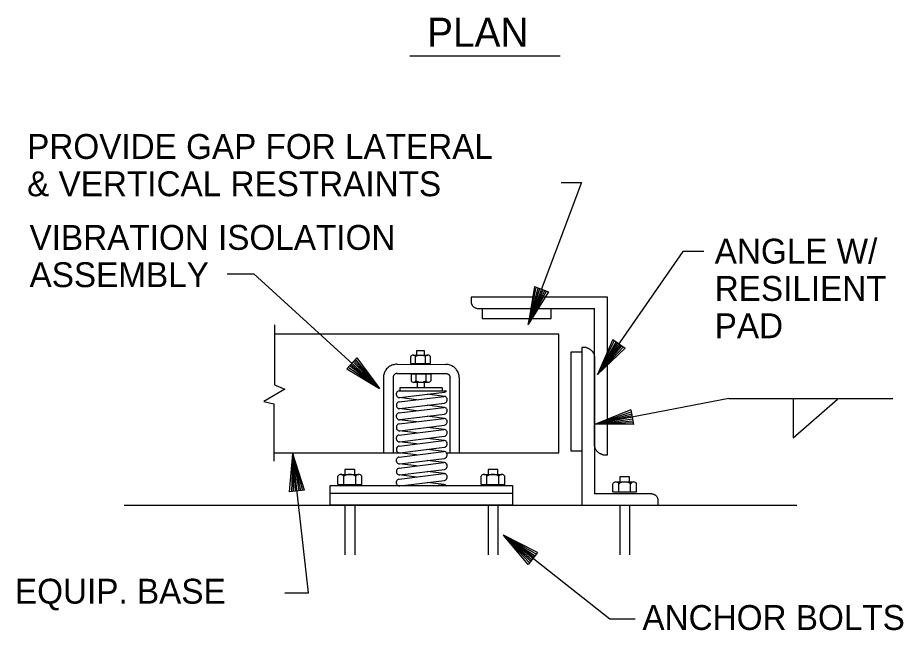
# Model space of a CAD drawing. Extents: x 9999.96 to 10005.26, y 9999.88 to 10002.38.
# Drawn here: x 10002.2227 to 10002.5788, y 10001.8155 to 10002.0618 of the extents above; entities that cross this region are included whole.
import ezdxf

# ---------------------------------------------------------------- set-up
doc = ezdxf.new("R2010")
doc.units = 0
doc.layers.add('Level 2', color=7, linetype='Continuous')

msp = doc.modelspace()

# ---------------------------------------------------------------- linework, layer by layer
at = {"layer": 'Level 2'}
for p, q in [((10002.3804, 10002.04644), (10002.44085, 10002.04644)), ((10002.43048, 10001.95363), (10002.42802, 10001.93847)), ((10002.42802, 10001.93847), (10002.4312, 10001.95335)), ((10002.42802, 10001.93847), (10002.43199, 10001.95308)), ((10002.42802, 10001.93847), (10002.43261, 10001.95282)), ((10002.43327, 10001.95259), (10002.42802, 10001.93847)), ((10002.42802, 10001.93847), (10002.43398, 10001.95231)), ((10002.42802, 10001.93847), (10002.43468, 10001.95206)), ((10002.42802, 10001.93847), (10002.43535, 10001.9518)), ((10002.43611, 10001.9515), (10002.42802, 10001.93847)), ((10002.43048, 10001.95363), (10002.43611, 10001.9515)), ((10002.4598, 10001.94941), (10002.40499, 10001.94941)), ((10002.40499, 10001.94941), (10002.40499, 10001.94773)), ((10002.4598, 10001.88604), (10002.4598, 10001.94941)), ((10002.40771, 10001.94486), (10002.45464, 10001.94486)), ((10002.45464, 10001.88964), (10002.45464, 10001.94486)), ((10002.44031, 10001.93446), (10002.32593, 10001.93446)), ((10002.44031, 10001.88671), (10002.44031, 10001.93446)), ((10002.46198, 10001.9324), (10002.45586, 10001.91831)), ((10002.45586, 10001.91831), (10002.4626, 10001.93196)), ((10002.45586, 10001.91831), (10002.46331, 10001.9315)), ((10002.45586, 10001.91831), (10002.46384, 10001.93109)), ((10002.46443, 10001.93071), (10002.45586, 10001.91831)), ((10002.45586, 10001.91831), (10002.46504, 10001.93027)), ((10002.45586, 10001.91831), (10002.46567, 10001.92985)), ((10002.46198, 10001.9324), (10002.46692, 10001.92895)), ((10002.44947, 10001.9291), (10002.44947, 10001.86574)), ((10002.4513, 10001.9291), (10002.44947, 10001.9291)), ((10002.45586, 10001.91831), (10002.46625, 10001.92943)), ((10002.46692, 10001.92895), (10002.45586, 10001.91831)), ((10002.35503, 10001.9206), (10002.3591, 10001.92505)), ((10002.35703, 10001.92282), (10002.36819, 10001.91269)), ((10002.36819, 10001.91269), (10002.35755, 10001.92336)), ((10002.36819, 10001.91269), (10002.35805, 10001.92393)), ((10002.36819, 10001.91269), (10002.35854, 10001.92446)), ((10002.3591, 10001.92505), (10002.36819, 10001.91269)), ((10002.38075, 10001.92279), (10002.38075, 10001.92554)), ((10002.38075, 10001.92279), (10002.38865, 10001.92279)), ((10002.38174, 10001.92614), (10002.38766, 10001.92614)), ((10002.38271, 10001.92279), (10002.38271, 10001.92554)), ((10002.38668, 10001.92279), (10002.38668, 10001.92554)), ((10002.38865, 10001.92279), (10002.38865, 10001.92552)), ((10002.45464, 10001.92551), (10002.45464, 10001.87028)), ((10002.35503, 10001.9206), (10002.36819, 10001.91269)), ((10002.36819, 10001.91269), (10002.35555, 10001.92118)), ((10002.36819, 10001.91269), (10002.3561, 10001.92181)), ((10002.36819, 10001.91269), (10002.35657, 10001.92229)), ((10002.37523, 10001.92241), (10002.3949, 10001.92236)), ((10002.36977, 10001.91704), (10002.36977, 10001.88671)), ((10002.37363, 10001.91714), (10002.37363, 10001.88671)), ((10002.37529, 10001.91871), (10002.39491, 10001.91871)), ((10002.38088, 10001.91851), (10002.38877, 10001.91851)), ((10002.38088, 10001.91851), (10002.38088, 10001.91576)), ((10002.38283, 10001.91851), (10002.38283, 10001.91576)), ((10002.3868, 10001.91851), (10002.3868, 10001.91576)), ((10002.38877, 10001.91851), (10002.38877, 10001.91578)), ((10002.39652, 10001.91704), (10002.39652, 10001.88671)), ((10002.40022, 10001.91704), (10002.40022, 10001.88671)), ((10002.39343, 10001.91298), (10002.3764, 10001.91298)), ((10002.3764, 10001.91298), (10002.3764, 10001.91173)), ((10002.38186, 10001.91517), (10002.38778, 10001.91517)), ((10002.38327, 10001.9152), (10002.38327, 10001.91296)), ((10002.38631, 10001.91296), (10002.38631, 10001.9152)), ((10002.39343, 10001.91298), (10002.39343, 10001.91173)), ((10002.37602, 10001.91173), (10002.39514, 10001.91173)), ((10002.38304, 10001.90816), (10002.37602, 10001.90901)), ((10002.37603, 10001.90729), (10002.39406, 10001.90951)), ((10002.37629, 10001.90902), (10002.39431, 10001.91124)), ((10002.39432, 10001.90951), (10002.38729, 10001.91038)), ((10002.50869, 10001.9086), (10002.45499, 10001.89832)), ((10002.50869, 10001.9086), (10002.57463, 10001.9086)), ((10002.53457, 10001.90857), (10002.53457, 10001.89282)), ((10002.53457, 10001.89282), (10002.55236, 10001.90845)), ((10002.37602, 10001.90285), (10002.39404, 10001.90507)), ((10002.3763, 10001.90458), (10002.39433, 10001.9068)), ((10002.39434, 10001.90507), (10002.3873, 10001.90594)), ((10002.38305, 10001.90372), (10002.37604, 10001.90457)), ((10002.37629, 10001.90015), (10002.39431, 10001.90236)), ((10002.39432, 10001.90064), (10002.38729, 10001.9015)), ((10002.46921, 10001.9041), (10002.45499, 10001.89832)), ((10002.45499, 10001.89832), (10002.46935, 10001.90335)), ((10002.45499, 10001.89832), (10002.46953, 10001.90253)), ((10002.45499, 10001.89832), (10002.46964, 10001.90186)), ((10002.46921, 10001.9041), (10002.47033, 10001.89818)), ((10002.38304, 10001.89928), (10002.37602, 10001.90014)), ((10002.37603, 10001.89842), (10002.39406, 10001.90064)), ((10002.3763, 10001.89571), (10002.39433, 10001.89793)), ((10002.46978, 10001.90118), (10002.45499, 10001.89832)), ((10002.45499, 10001.89832), (10002.46992, 10001.90044)), ((10002.45499, 10001.89832), (10002.47006, 10001.8997)), ((10002.45499, 10001.89832), (10002.47019, 10001.89899)), ((10002.47033, 10001.89818), (10002.45499, 10001.89832)), ((10002.37602, 10001.89398), (10002.39404, 10001.8962)), ((10002.38305, 10001.89484), (10002.37604, 10001.8957)), ((10002.39434, 10001.8962), (10002.3873, 10001.89706)), ((10002.38304, 10001.89041), (10002.37602, 10001.89126)), ((10002.37603, 10001.88954), (10002.39406, 10001.89176)), ((10002.37629, 10001.89127), (10002.39431, 10001.89349)), ((10002.39432, 10001.89176), (10002.38729, 10001.89263)), ((10002.37602, 10001.8851), (10002.39404, 10001.88732)), ((10002.3763, 10001.88683), (10002.39433, 10001.88905)), ((10002.39434, 10001.88732), (10002.3873, 10001.88819)), ((10002.37686, 10001.88671), (10002.32565, 10001.88671)), ((10002.33197, 10001.8711), (10002.33329, 10001.8864)), ((10002.33329, 10001.8864), (10002.33278, 10001.87119)), ((10002.335, 10001.87143), (10002.33329, 10001.8864)), ((10002.33796, 10001.87177), (10002.33329, 10001.8864)), ((10002.33329, 10001.8864), (10002.33351, 10001.87126)), ((10002.33329, 10001.8864), (10002.33636, 10001.87157)), ((10002.33329, 10001.8864), (10002.33425, 10001.87135)), ((10002.33329, 10001.8864), (10002.3357, 10001.87152)), ((10002.33329, 10001.8864), (10002.3372, 10001.87169)), ((10002.38305, 10001.88597), (10002.37604, 10001.88682)), ((10002.37629, 10001.8824), (10002.39431, 10001.8846)), ((10002.39432, 10001.88288), (10002.38729, 10001.88374)), ((10002.44031, 10001.88671), (10002.3952, 10001.88671)), ((10002.45797, 10001.88604), (10002.4598, 10001.88604)), ((10002.38304, 10001.88152), (10002.37602, 10001.88239)), ((10002.37603, 10001.88067), (10002.39406, 10001.88288)), ((10002.3763, 10001.87796), (10002.39433, 10001.88017)), ((10002.35147, 10001.87408), (10002.35147, 10001.87742)), ((10002.35267, 10001.87815), (10002.35983, 10001.87815)), ((10002.35383, 10001.87408), (10002.35383, 10001.87742)), ((10002.35864, 10001.87408), (10002.35864, 10001.87742)), ((10002.36102, 10001.87408), (10002.36102, 10001.8774)), ((10002.37602, 10001.87623), (10002.39404, 10001.87844)), ((10002.38305, 10001.87708), (10002.37604, 10001.87795)), ((10002.39434, 10001.87844), (10002.3873, 10001.8793)), ((10002.40899, 10001.87408), (10002.40899, 10001.87742)), ((10002.41019, 10001.87815), (10002.41735, 10001.87815)), ((10002.41135, 10001.87408), (10002.41135, 10001.87742)), ((10002.41616, 10001.87408), (10002.41616, 10001.87742)), ((10002.41854, 10001.87408), (10002.41854, 10001.8774)), ((10002.35147, 10001.87408), (10002.36102, 10001.87408)), ((10002.37629, 10001.87352), (10002.39431, 10001.87573)), ((10002.39405, 10001.87404), (10002.38729, 10001.87486)), ((10002.3898, 10001.87352), (10002.39405, 10001.87404)), ((10002.40899, 10001.87408), (10002.41854, 10001.87408)), ((10002.46199, 10001.87107), (10002.46199, 10001.87441)), ((10002.46319, 10001.87514), (10002.47035, 10001.87514)), ((10002.46435, 10001.87107), (10002.46435, 10001.87441)), ((10002.46916, 10001.87107), (10002.46916, 10001.87441)), ((10002.47154, 10001.87107), (10002.47154, 10001.87439)), ((10002.33796, 10001.87177), (10002.33197, 10001.8711)), ((10002.34829, 10001.87057), (10002.42169, 10001.87057)), ((10002.47757, 10001.87028), (10002.45464, 10001.87028)), ((10002.46199, 10001.87107), (10002.47154, 10001.87107)), ((10002.26555, 10001.86574), (10002.53604, 10001.86574)), ((10002.35429, 10001.86575), (10002.35429, 10001.84577)), ((10002.35822, 10001.86575), (10002.35822, 10001.84577)), ((10002.41181, 10001.86575), (10002.41181, 10001.84577)), ((10002.41574, 10001.86575), (10002.41574, 10001.84577)), ((10002.44947, 10001.86574), (10002.48029, 10001.86574)), ((10002.46481, 10001.86575), (10002.46481, 10001.84577)), ((10002.46874, 10001.86575), (10002.46874, 10001.84577)), ((10002.48029, 10001.86574), (10002.48029, 10001.86742)), ((10002.42992, 10001.84435), (10002.41808, 10001.85368)), ((10002.42802, 10001.84198), (10002.41808, 10001.85368)), ((10002.43176, 10001.84671), (10002.41808, 10001.85368)), ((10002.41808, 10001.85368), (10002.42899, 10001.84318)), ((10002.41808, 10001.85368), (10002.43078, 10001.84543)), ((10002.41808, 10001.85368), (10002.42853, 10001.84261)), ((10002.41808, 10001.85368), (10002.42945, 10001.84377)), ((10002.41808, 10001.85368), (10002.43034, 10001.84492)), ((10002.41808, 10001.85368), (10002.43128, 10001.8461)), ((10002.43176, 10001.84671), (10002.42802, 10001.84198))]:
    msp.add_line(p, q, dxfattribs=at)
for points in [[(10002.44119, 10001.99555), (10002.44934, 10001.99555), (10002.42802, 10001.93847)], [(10002.49858, 10001.96777), (10002.49016, 10001.96777), (10002.45586, 10001.91831)], [(10002.30692, 10001.95878), (10002.31759, 10001.95878), (10002.36819, 10001.91269)], [(10002.40501, 10001.94794), (10002.405, 10001.94775), (10002.405, 10001.94755), (10002.40502, 10001.94736), (10002.40505, 10001.94717), (10002.40509, 10001.94698), (10002.40516, 10001.94679), (10002.40522, 10001.94661), (10002.4053, 10001.94644), (10002.4054, 10001.94626), (10002.4055, 10001.9461), (10002.40561, 10001.94595), (10002.40574, 10001.94579), (10002.40588, 10001.94566), (10002.40602, 10001.94553), (10002.40618, 10001.94541), (10002.40633, 10001.9453), (10002.40651, 10001.9452), (10002.40668, 10001.94511), (10002.40686, 10001.94504), (10002.40704, 10001.94498), (10002.40723, 10001.94493), (10002.40743, 10001.9449), (10002.40761, 10001.94486), (10002.40771, 10001.94486)], [(10002.40947, 10001.94475), (10002.40947, 10001.94083), (10002.43723, 10001.94083), (10002.43723, 10001.94491)], [(10002.32593, 10001.93828), (10002.32593, 10001.91414), (10002.33014, 10001.91245), (10002.32171, 10001.90739), (10002.32565, 10001.90654), (10002.32565, 10001.8834)], [(10002.38632, 10001.92616), (10002.38632, 10001.92781), (10002.38308, 10001.92781), (10002.38308, 10001.92616)], [(10002.44947, 10001.92722), (10002.44509, 10001.92722), (10002.44509, 10001.88765), (10002.44947, 10001.88765)], [(10002.4513, 10001.9291), (10002.45149, 10001.92905), (10002.45169, 10001.929), (10002.45188, 10001.92894), (10002.45206, 10001.92886), (10002.45224, 10001.92878), (10002.45242, 10001.92869), (10002.45259, 10001.92859), (10002.45276, 10001.92849), (10002.45293, 10001.92838), (10002.45308, 10001.92825), (10002.45324, 10001.92813), (10002.45339, 10001.92798), (10002.45352, 10001.92784), (10002.45366, 10001.9277), (10002.45378, 10001.92754), (10002.4539, 10001.92738), (10002.45401, 10001.92721), (10002.45411, 10001.92704), (10002.45421, 10001.92686), (10002.45429, 10001.92669), (10002.45438, 10001.9265), (10002.45444, 10001.92631), (10002.4545, 10001.92613), (10002.45455, 10001.92594), (10002.45465, 10001.92551)], [(10002.37523, 10001.92241), (10002.37481, 10001.9224), (10002.37439, 10001.92234), (10002.37398, 10001.92226), (10002.37357, 10001.92215), (10002.37308, 10001.922), (10002.3727, 10001.92182), (10002.37233, 10001.92161), (10002.37198, 10001.92139), (10002.37165, 10001.92113), (10002.37134, 10001.92083), (10002.37105, 10001.92053), (10002.37079, 10001.9202), (10002.37056, 10001.91984), (10002.37035, 10001.91948), (10002.37018, 10001.91909), (10002.37003, 10001.9187), (10002.36992, 10001.91829), (10002.36983, 10001.91789), (10002.36978, 10001.91747), (10002.36977, 10001.91704)], [(10002.40022, 10001.91704), (10002.4002, 10001.91746), (10002.40015, 10001.91788), (10002.40007, 10001.91828), (10002.39996, 10001.91869), (10002.39981, 10001.91908), (10002.39964, 10001.91946), (10002.39944, 10001.91982), (10002.3992, 10001.92017), (10002.39894, 10001.9205), (10002.39866, 10001.9208), (10002.39835, 10001.92108), (10002.39802, 10001.92134), (10002.39768, 10001.92157), (10002.39731, 10001.92178), (10002.39694, 10001.92196), (10002.39654, 10001.9221), (10002.39614, 10001.92221), (10002.39573, 10001.92229), (10002.39531, 10001.92234), (10002.3949, 10001.92236)], [(10002.37529, 10001.91871), (10002.37516, 10001.9187), (10002.37503, 10001.91869), (10002.3749, 10001.91867), (10002.37477, 10001.91863), (10002.37465, 10001.91858), (10002.37453, 10001.91852), (10002.37442, 10001.91846), (10002.37431, 10001.91839), (10002.37421, 10001.91831), (10002.3741, 10001.91822), (10002.37402, 10001.91813), (10002.37394, 10001.91802), (10002.37386, 10001.91791), (10002.3738, 10001.91779), (10002.37375, 10001.91768), (10002.3737, 10001.91755), (10002.37367, 10001.91743), (10002.37365, 10001.9173), (10002.37363, 10001.91717), (10002.37363, 10001.91714)], [(10002.39491, 10001.91871), (10002.39503, 10001.91871), (10002.39516, 10001.91869), (10002.39528, 10001.91867), (10002.39541, 10001.91864), (10002.39553, 10001.91859), (10002.39565, 10001.91854), (10002.39576, 10001.91848), (10002.39586, 10001.91841), (10002.39597, 10001.91833), (10002.39606, 10001.91824), (10002.39615, 10001.91815), (10002.39623, 10001.91805), (10002.3963, 10001.91795), (10002.39636, 10001.91783), (10002.39642, 10001.91772), (10002.39647, 10001.91759), (10002.3965, 10001.91747), (10002.39652, 10001.91734), (10002.39654, 10001.91722), (10002.39654, 10001.91709)], [(10002.45797, 10001.88604), (10002.45778, 10001.88609), (10002.45758, 10001.88615), (10002.4574, 10001.88621), (10002.45721, 10001.88628), (10002.45703, 10001.88636), (10002.45685, 10001.88646), (10002.45668, 10001.88655), (10002.45651, 10001.88666), (10002.45634, 10001.88677), (10002.45619, 10001.8869), (10002.45603, 10001.88702), (10002.45589, 10001.88717), (10002.45575, 10001.8873), (10002.45561, 10001.88745), (10002.45549, 10001.8876), (10002.45538, 10001.88777), (10002.45526, 10001.88794), (10002.45516, 10001.8881), (10002.45506, 10001.88828), (10002.45498, 10001.88846), (10002.4549, 10001.88865), (10002.45483, 10001.88883), (10002.45477, 10001.88902), (10002.45472, 10001.88921), (10002.45463, 10001.88964)], [(10002.33016, 10001.83057), (10002.33957, 10001.83057), (10002.33329, 10001.8864)], [(10002.35822, 10001.87817), (10002.35822, 10001.88017), (10002.35429, 10001.88017), (10002.35429, 10001.87817)], [(10002.41574, 10001.87817), (10002.41574, 10001.88017), (10002.41181, 10001.88017), (10002.41181, 10001.87817)], [(10002.46874, 10001.87516), (10002.46874, 10001.87716), (10002.46481, 10001.87716), (10002.46481, 10001.87516)], [(10002.48027, 10001.86721), (10002.48028, 10001.8674), (10002.48028, 10001.86759), (10002.48026, 10001.86778), (10002.48023, 10001.86798), (10002.48019, 10001.86817), (10002.48013, 10001.86835), (10002.48006, 10001.86853), (10002.47998, 10001.86871), (10002.47989, 10001.86889), (10002.47978, 10001.86904), (10002.47967, 10001.8692), (10002.47954, 10001.86935), (10002.47941, 10001.86949), (10002.47926, 10001.86961), (10002.4791, 10001.86974), (10002.47895, 10001.86984), (10002.47877, 10001.86995), (10002.4786, 10001.87003), (10002.47842, 10001.8701), (10002.47824, 10001.87017), (10002.47805, 10001.87022), (10002.47785, 10001.87025), (10002.47767, 10001.87028), (10002.47757, 10001.87028)], [(10002.47092, 10001.81995), (10002.4608, 10001.81995), (10002.41808, 10001.85368)]]:
    msp.add_lwpolyline(points, dxfattribs=at)
msp.add_lwpolyline([(10002.42169, 10001.86575), (10002.34829, 10001.86575), (10002.34829, 10001.87368), (10002.42169, 10001.87368)], close=True, dxfattribs=at)
for centre, radius, start, end in [((10002.38173, 10001.92503), 0.0011, 27.8877, 152.0342), ((10002.38469, 10001.92249), 0.00365, 57.0062, 122.943), ((10002.38765, 10001.92502), 0.0011, 26.7827, 151.8391), ((10002.38186, 10001.91627), 0.0011, 207.9658, 332.1123), ((10002.38482, 10001.91881), 0.00365, 237.057, 302.9938), ((10002.38778, 10001.91628), 0.0011, 208.1609, 333.2173), ((10002.35266, 10001.8768), 0.00134, 27.8877, 152.0342), ((10002.35624, 10001.87372), 0.00441, 57.0062, 122.943), ((10002.35982, 10001.87679), 0.00134, 26.7827, 151.8391), ((10002.41018, 10001.8768), 0.00134, 27.8877, 152.0342), ((10002.41376, 10001.87372), 0.00441, 57.0062, 122.943), ((10002.41734, 10001.87679), 0.00134, 26.7827, 151.8391), ((10002.46318, 10001.87379), 0.00134, 27.8877, 152.0342), ((10002.46676, 10001.87071), 0.00441, 57.0062, 122.943), ((10002.47034, 10001.87378), 0.00134, 26.7827, 151.8391)]:
    msp.add_arc(centre, radius, start, end, dxfattribs=at)
for centre, major_axis, start_param, end_param in [((10002.37615, 10001.91037), (0, -0.00136), 3.251722, 6.393315), ((10002.39419, 10001.90815), (0, 0.00136), 3.251722, 6.393315), ((10002.39418, 10001.91259), (0, 0.00136), 3.251722, 4.030489), ((10002.37617, 10001.90593), (0, -0.00136), 3.251722, 6.393315), ((10002.39418, 10001.90371), (0, 0.00136), 3.251722, 6.393315), ((10002.37615, 10001.90149), (0, -0.00136), 3.251722, 6.393315), ((10002.37617, 10001.89706), (0, -0.00136), 3.251722, 6.393315), ((10002.39419, 10001.89927), (0, 0.00136), 3.251722, 6.393315), ((10002.39418, 10001.89484), (0, 0.00136), 3.251722, 6.393315), ((10002.37615, 10001.89262), (0, -0.00136), 3.251722, 6.393315), ((10002.39419, 10001.8904), (0, 0.00136), 3.251722, 6.393315), ((10002.37617, 10001.88818), (0, -0.00136), 3.251722, 6.393315), ((10002.39418, 10001.88596), (0, 0.00136), 3.251722, 6.393315), ((10002.37615, 10001.88374), (0, -0.00136), 3.251722, 6.393315), ((10002.37617, 10001.87931), (0, -0.00136), 3.251722, 6.393315), ((10002.39419, 10001.88152), (0, 0.00136), 3.251722, 6.393315), ((10002.39418, 10001.87709), (0, 0.00136), 3.251722, 6.393315), ((10002.37615, 10001.87487), (0, -0.00136), 3.251722, 6.393315), ((10002.39405, 10001.87268), (0, 0.00136), 5.361733, 6.39416)]:
    msp.add_ellipse(centre, major_axis=major_axis, ratio=0.9, start_param=start_param, end_param=end_param, dxfattribs=at)

# ---------------------------------------------------------------- texts
for s, height, p in [('PLAN', 0.011667, (10002.38732, 10002.05009)), ('PROVIDE GAP FOR LATERAL', 0.01, (10002.22651, 10002.00499)), ('& VERTICAL RESTRAINTS', 0.01, (10002.22651, 10001.98999)), ('VIBRATION ISOLATION', 0.01, (10002.22747, 10001.96843)), ('ANGLE W/', 0.01, (10002.50296, 10001.9629)), ('ASSEMBLY', 0.01, (10002.22747, 10001.95343)), ('RESILIENT ', 0.01, (10002.50296, 10001.9479)), ('PAD', 0.01, (10002.50296, 10001.9329)), ('EQUIP. BASE', 0.01, (10002.22161, 10001.82617)), ('ANCHOR BOLTS', 0.01, (10002.47389, 10001.8156))]:
    msp.add_text(s, height=height, dxfattribs=at).set_placement(p)

doc.saveas('drawing.dxf')
